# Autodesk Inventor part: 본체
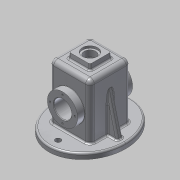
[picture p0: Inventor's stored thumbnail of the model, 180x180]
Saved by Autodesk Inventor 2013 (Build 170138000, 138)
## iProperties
Created: 2017-07
Part Number: 본체
Material: 알루미늄 6061
Document SubType Name: Modeling
Designer: Administrator
Density: 2.71 g/cm^3
Mass: 894.996 g
Surface Area: 993.064 cm^2
Volume: 330.257 cm^3
Author: Administrator
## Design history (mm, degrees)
sketch "스케치2"
  geometry: L1 (0, 0)-(74, 0); L2 (74, 0)-(74, 110); L3 (74, 110)-(0, 110); L4 (0, 110)-(0, 0)
  constraints: 8 end point, 2 parallel, 1 horizontal, 1 perpendicular
  dimensions: "d2" = 74 distance of L2.end L3.end; "d4" = 110 distance of L1.end L2.end
extrude "돌출1" new body sketch "스케치2" distance "d5" = 74; taper "d6" = 0 deg
feature "쉘1" dims "d7" = 5
sketch "스케치3" dims "d8" = 65, "d10" = 75
  geometry: L1 (5, 5)-(5, 69) reference; L2 (5, 69)-(69, 69) reference; L3 (69, 69)-(69, 5) reference; L4 (69, 5)-(5, 5) reference; L5 (0, 0)-(0, 74) reference; L6 (0, 0)-(74, 0) reference; L7 (74, 74)-(74, 0) reference; L8 (0, 74)-(74, 74) reference; L9 (37, 0)-(37, 74); L10 (74, 37)-(0, 37); 1 further point; 1 other entity
  constraints: 4 end point, 4 midpoint, 1 vertical, 2 other
  dimensions: "d11" = 0 distance from line of L9 point (37, 37); "d12" = 0 distance from line of L10 point (37, 37)
extrude "돌출2" join sketch "스케치3" distance "d13" = 10; taper "d14" = 0 deg
fillet "모깎기1" dims "d15" = 8, "d16" = 3
sketch "스케치4"
  geometry: L1 (0, -89)-(0, 0) reference; L2 (94, -102)-(-36, -102) reference; C1 r 27.5 at (29, -47); 1 further point
  constraints: 1 centre point
  dimensions: "d17" = 55 distance from line of L2 C1.centre; "d18" = 29 distance from line of C1.centre L1; "d19" = 55 diameter of C1
extrude "돌출3" join sketch "스케치4" distance "d20" = 13; taper "d21" = 0 deg
sketch "스케치5"
  geometry: L1 (58, 0)-(58, -89) reference; L2 (-36, 13)-(94, 13) reference; C1 r 27.5 at (29, -42); 1 further point
  constraints: 1 centre point
  dimensions: "d22" = 55 distance from line of L2 C1.centre; "d23" = 55 diameter of C1; "d24" = 29 distance from line of L1 C1.centre
extrude "돌출4" join sketch "스케치5" distance "d25" = 13; taper "d26" = 0 deg
sketch "스케치6"
  geometry: L1 (58, 0)-(58, -102) reference; L2 (0, 0)-(58, 0) reference; L3 (29, -55)-(56.5, -55); L4 (29, -55)-(1.5, -55); A1 r 27.5 centre (29, -55) between (56.5, -55) and (1.5, -55); 1 further point
  constraints: 4 end point, 2 point on circle, 1 centre point, 1 collinear, 1 perpendicular
  dimensions: "d27" = 55 distance from line of L2 L3.start; "d28" = 29 distance from line of L1 L3.start; "d29" = 55 diameter of A1; "d130" = 55 distance of L3.end L4.end (derived)
extrude "돌출5" join sketch "스케치6" distance "d30" = 7; taper "d31" = -45 deg
sketch "스케치7"
  geometry: L1 (58, 0)-(58, -102) reference; L2 (58, -102)-(0, -102) reference; L3 (0, -102)-(0, 0) reference; L4 (29, -47)-(1.5, -47); L5 (29, -47)-(56.5, -47); A1 r 27.5 centre (29, -47) between (1.5, -47) and (56.5, -47); 1 further point
  constraints: 4 end point, 2 point on circle, 1 centre point, 1 collinear, 1 perpendicular
  dimensions: "d32" = 55 distance from line of L2 L4.start; "d33" = 29 distance from line of L1 L4.start; "d34" = 55 diameter of A1; "d129" = 55 distance of L5.end L4.end (derived)
extrude "돌출6" join sketch "스케치7" distance "d35" = 7; taper "d36" = -45 deg
sketch "스케치8"
  geometry: C1 r 27.5 at (0, 0) reference; C2 r 16 at (0, 0); 1 further point
  constraints: 1 centre point, 1 coincident
  dimensions: "d37" = 32 diameter of C2
extrude "돌출7" cut sketch "스케치8" stored distance "d39" = 7; taper "d40" = 0 deg
sketch "스케치9"
  geometry: C1 r 5 at (-37, -21); C2 r 5 at (-37, 95); 2 further points; 1 other entity
  constraints: 2 centre point, 1 other
  dimensions: "d41" = 0 horizontal distance of point (-37, 37) C1.centre; "d42" = 0 horizontal distance of C2.centre point (-37, 37); "d43" = 58 distance of point (-37, 37) C1.centre; "d44" = 58 distance of C2.centre point (-37, 37); "d45" = 10 diameter of C1; "d46" = 10 diameter of C2
extrude "돌출8" cut sketch "스케치9" stored distance "d47" = 7; taper "d48" = 0 deg
sketch "스케치10"
  geometry: L1 (0, -58)-(0, 0) reference; L2 (58, -58)-(0, -58) reference; L3 (9, -49)-(49, -49); L4 (49, -49)-(49, -9); L5 (49, -9)-(9, -9); L6 (9, -9)-(9, -49); 1 further point
  constraints: 8 end point, 2 parallel, 1 horizontal, 1 perpendicular
  dimensions: "d53" = 40 distance of L5.end L3.start; "d54" = 40 distance of L4.end L5.end; "d55" = 9 distance between parallel lines of L6 L1; "d56" = 9 distance between parallel lines of L2 L3
extrude "돌출9" join sketch "스케치10" distance "d57" = 10; taper "d58" = -5 deg
fillet "모깎기2" dims "d59" = 3
sketch "스케치11"
  geometry: L1 (0, -58)-(0, 0) reference; L2 (0, 0)-(58, 0) reference; C1 r 14 at (29, -29); 1 further point
  constraints: 1 centre point
  dimensions: "d60" = 29 distance from line of C1.centre L1; "d61" = 29 distance from line of C1.centre L2; "d62" = 28 diameter of C1
extrude "돌출10" cut sketch "스케치11" distance "d63" = 4; taper "d64" = 0 deg
sketch "스케치12"
  geometry: C1 r 14 at (0, 0) reference; C2 r 10.5 at (0, 0); 1 further point
  constraints: 1 centre point, 1 coincident
  dimensions: "d65" = 21 diameter of C2
extrude "돌출11" cut sketch "스케치12" stored distance "d67" = 4; taper "d68" = 0 deg
sketch "스케치13" dims "d69" = 45
  geometry: C1 r 16 at (0, 0) reference; C2 r 27.5 at (0, 0) reference; 3 further points
  constraints: 1 coincident, 1 vertical alignment, 2 other
  dimensions: "d71" = 0 horizontal distance of C1.centre point (0, 22.5)
hole "구멍1" sketch "스케치13" at (0, 22.5) diameter "d72" = 3.242; stored, may be unused: countersink angle "d76" = 90 deg, drill point angle "d78" = 118 deg; dims "d73" = 8, "d74" = 4, "d75" = 2, "d77" = 10
sketch "스케치14" dims "d82" = 45
  geometry: C1 r 16 at (0, 0) reference; C2 r 27.5 at (0, 0) reference; 3 further points
  constraints: 1 coincident, 1 vertical alignment, 2 other
  dimensions: "d84" = 0 horizontal distance of C1.centre point (0, -22.5)
hole "구멍2" sketch "스케치14" at (0, -22.5) diameter "d85" = 3.242; stored, may be unused: countersink angle "d89" = 90 deg, drill point angle "d91" = 118 deg; dims "d86" = 8, "d87" = 4, "d88" = 2, "d90" = 10
node "작업 평면2"
sketch "스케치15"
  geometry: L1 (94, -92)-(-36, -92) reference; L2 (-8, -89)-(-8, 0) reference; L3 (66, 0)-(66, -89) reference; L4 (-8, -19.806)-(-26, -92); L5 (66, -19.806)-(84, -92); L6 (94, -92)-(-36, -92) reference; L7 (94, -102)-(-36, -102) reference; L8 (-36, -92)-(-36, -57); 1 further point
  constraints: 6 end point, 4 point on line, 1 equal length, 1 perpendicular
  dimensions: "d95" = 10 distance of L1.start L5.end; "d96" = 10 distance of L1.end L4.end; "d111" = 14 deg angle of L4 L8
  node "투영된 루프1"
fillet "모깎기3" dims "d99" = 0.5
chamfer "모따기1" distance "d101" = 1; stored, may be unused: second distance "d102" = 2, angle "d103" = 45 deg
sketch "스케치16"
  geometry: L1 (0, 0)-(0, 89) reference; L2 (51.066, 7.438)-(6.934, 7.438); L3 (6.934, 7.438)-(6.934, 16.562); L4 (6.934, 16.562)-(51.066, 16.562); L5 (51.066, 16.562)-(51.066, 7.438); L6 (29, 7.438)-(29, 16.562); L7 (51.066, 12)-(6.934, 12); L8 (12.863, -18)-(45.137, -18) reference; 2 further points
  constraints: 4 end point, 4 midpoint, 2 other
  dimensions: "d104" = 30 distance between parallel lines of L7 L8; "d105" = 29 distance between parallel lines of L1 L6; "d106" = 44.1319 distance of L2.start L2.end; "d107" = 9.12397 distance of L2.end L3.end
feature "엠보싱1" sketch "스케치16" dims "d2" = 74, "d4" = 110, "d10" = 75, "d108" = 0.5, "d109" = 0
feature "리브1" dims "d112" = 1, "d113" = 10, "d114" = 0, "d115" = 0, "d116" = 1, "d117" = 1
sketch "스케치17"
  geometry: L1 (94, -92)-(-36, -92) reference; L2 (66, 0)-(66, -89) reference; L3 (84, -92)-(66, -19.806); L4 (94, -92)-(94, -53); 1 further point
  constraints: 4 end point, 2 point on line, 1 parallel
  dimensions: "d118" = 39 distance of L1.start L4.end; "d119" = 14 deg angle of L4 L3; "d120" = 10 distance of L1.start L3.start
feature "리브2" sketch "스케치17" dims "d121" = 1, "d122" = 10, "d123" = 0, "d124" = 0, "d125" = 1, "d126" = 1
fillet "모깎기4" dims "d127" = 3
fillet "모깎기5" dims "d128" = 3
node "솔리드1"
pattern_circular "원형 패턴1" dims angle "d80" = 360 deg
pattern_circular "원형 패턴2" dims angle "d93" = 360 deg
